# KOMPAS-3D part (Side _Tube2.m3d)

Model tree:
1. Plane XY
2. Plane ZX
3. Plane ZY
4. X Axis
5. Y Axis
6. Z Axis
7. Origin
8. Sketch:1
9. Extrude:1
     Wall Thickness 1 = 1; Wall Thickness 2 = 10; Distance 1 = 2489; Distance 2 = 2000

Referenced files in D:\Documents and Settings\kashirsky\Рабочий стол\Cottage\: Cottage_balcony.a3d, Cottage.a3d
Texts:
  Steel DIN 17102
  Three Point Plane
  Plane at Angle
  Line and Point Plane
  Axis through Two Vertices
  Axis of Feature
  Axis of Conical Surface
  Axis through Edge
  Trim by Surface
  Trim by Sketch
  Feature with No History
  Intersection Axis of Two Planes
  Two Line Plane
  Line and Face Plane
  Bend by line
  Hole in sheet body
  Cut in sheet body
  Point in CM
  Linear Dimension from Line to Point
  Surface Finish Symbol
  Geometric Tolerance Symbol
  Leader #1
  Leader #2
  Leader #3
  Shape Deviations and Datum
  Node point number
  Mark of coordination axis
  Node point designation
  Mark/Reference designation with leader
  Mark/reference designation on line
  Mark/Reference designation without leader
